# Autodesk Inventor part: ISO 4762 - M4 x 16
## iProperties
Created: 2009-02
Part Number: ISO 4762 - M4 x 16
Material: EdelStahl - 440C
Description: Innensechskantschraube
Document SubType Name: Modeling
Standard: ISO 4762
Designer: UR
Standard Revision: 1998
Standards Organization: DIN
Language: de-DE
Size Designation: M4 x 16
Categories: <MemberInstance><Categories><Category DisplayName="Verbindungselemente" InternalName="e4da775c-781d-43d5-af7c-5136215cf5a6" Mnemonic="FSTN"><Category DisplayNam
Density: 7.75 g/cm^3
IsCustomPart: 0
Author: UR
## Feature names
1. Körper [Revolution]
2. Loch [Extrusion]
3. Rundung1 [Fillet]
4. Fase1 [Chamfer]
5. Fillet2
